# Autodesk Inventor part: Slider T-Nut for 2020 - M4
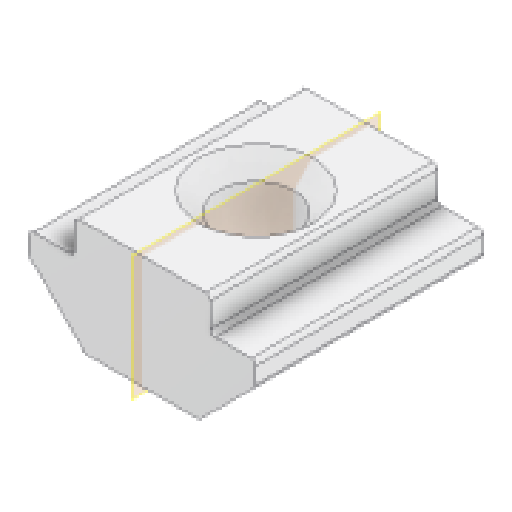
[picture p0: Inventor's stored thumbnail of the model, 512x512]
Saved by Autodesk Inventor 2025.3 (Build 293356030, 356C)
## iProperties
Created: 2018-12
Part Number: Slider T-Nut for 2020 - M4
Material: Steel
Document SubType Name: Modeling
Designer: 18907419
Density: 7.85 g/cm^3
Appearance: Acciaio
Sending System: Autodesk Translation Framework v7.6.0.251
Preprocessor: ST-DEVELOPER v17.2
Title: /Users/nikolaj/Library/Mobile Documents/com~apple~CloudDocs/3D printer/Mit byg/GrabCAD/T-Nut/Slider T-Nut for 2020 - M4.step
Author: nikolaj_tc@msn.com
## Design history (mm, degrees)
node "Body1"
node "Piano di lavoro1"
node "Solido1"
